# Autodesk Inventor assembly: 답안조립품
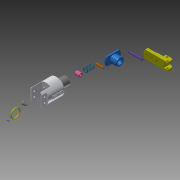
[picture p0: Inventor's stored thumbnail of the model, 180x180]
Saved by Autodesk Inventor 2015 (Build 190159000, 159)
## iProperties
Created: 2019-02
Part Number: 답안조립품
Document SubType Name: Assembly
Designer: now
Author: now
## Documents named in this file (11)
- C:\Users\now\Desktop\490207V1017\답안조립품.iam
- C:\Users\now\Desktop\490207V1017\E-링.ipt
- C:\Users\now\Desktop\490207V1017\O-링.ipt
- C:\Users\now\Desktop\490207V1017\가이드핀.ipt
- C:\Users\now\Desktop\490207V1017\본체.ipt
- C:\Users\now\Desktop\490207V1017\부시.ipt
- C:\Users\now\Desktop\490207V1017\스프링.ipt
- C:\Users\now\Desktop\490207V1017\평행핀 6x28.ipt
- C:\Users\now\Desktop\490207V1017\피스톤.ipt
- C:\Users\now\Desktop\490207V1017\핀.ipt
- C:\Users\now\Desktop\490207V1017\핑거.ipt
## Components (6 placed, 6 different names)
1. E-링:1
2. O-링:1
3. 가이드핀:1
4. 피스톤:1
5. 핀:1
6. 핑거:1
